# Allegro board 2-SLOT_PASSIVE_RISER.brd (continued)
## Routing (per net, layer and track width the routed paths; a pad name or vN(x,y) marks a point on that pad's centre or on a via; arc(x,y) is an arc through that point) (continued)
I2C_EMC1413_SCL: length 2.7
  TOP w0.117: U2.10 75.92,29.7 76.44,30.23 v1(76.65,30.23) 76.8,30.23 77.05,29.97 R59.2
I2C_EMC1413_SDA: length 2.6
  TOP w0.117: R41.2 77.29,28.8 v1(76.72,28.8) 76.32,29.2 U2.9
I2C_FRU_SCL: length 2.3
  TOP w0.117: U3.6 136.2,44.83 v1(135.27,44.83) 135.01,44.83 R58.2
I2C_FRU_SDA: length 2
  TOP w0.117: U3.5 135.38,46.54 v1(135.32,46.48) R40.2
I2C_MB_RISER_SCL: length 61.6
  TOP w0.117: R27.2 146.55,37.82 v1(146.52,37.8) 146.49,37.82 R57.1
  BOTTOM w0.117: v1(146.52,37.8) 146.65,37.8 147.51,36.93 147.51,27.71 142.28,22.48 121.58,22.48 119.94,20.84 119.94,18.77 118.99,17.82 118.99,14.39 119.94,13.44 119.94,12.06 119.73,11.85 119.73,11.85 119.43,11.56 119.43,11 120.22,10.21 120.22,6.47 119.78,6.03 J3.B5
I2C_MB_RISER_SDA: length 63.9
  TOP w0.117: R17.1 145.76,38.84 146.27,39.34 v1(146.55,39.34) 146.81,39.34 R26.2
  BOTTOM w0.117: v1(146.55,39.34) 145.94,38.73 145.94,37.49 146.72,36.71 146.72,36.71 147.04,36.39 147.04,36.39 147.08,36.35 147.08,28.02 141.91,22.85 121.42,22.85 119.57,21 119.57,18.92 118.61,17.96 118.61,14.25 119.57,13.28 119.57,12.22 119.06,11.71 119.06,10.85 119.85,10.06 119.85,6.63 118.78,5.55 J3.B6
I2C_PCA9548_SCL: length 2.9
  TOP w0.117: R57.2 144.7,37.9 v1(143.12,37.9) U1.22
I2C_PCA9548_SDA: length 3.3
  TOP w0.117: U1.23 143.09,38.55 v1(143.7,39.17) 144.45,39.17 R17.2
I2C_SLOT1_R_SCL: length 5.4
  TOP w0.117: J1.B5 119.78,19.71 121.27,21.21 R9.2
I2C_SLOT1_R_SDA: length 3.4
  TOP w0.117: R10.2 120.26,21.21 118.78,19.73 J1.B6
I2C_SLOT1_SCL: length 20.3
  TOP w0.117: R9.1 121.27,23.62 121.91,24.26 122.67,24.26 122.8,24.38 122.8,25.17 R39.2 123.54,25.91 125.72,25.91 125.97,26.16 125.97,26.92 125.68,27.22 Q4.S 124,27.49 124.32,27.81 125.59,27.81 v1(129.02,31.24) 129.66,31.88 129.66,33.93 R83.2
I2C_SLOT1_SDA: length 20
  TOP w0.117: R10.1 120.26,23.37 120.77,23.88 120.77,25.37 121.06,25.67 R37.2 121.27,25.88 120.57,26.58 Q2.S 120.57,28.05 120.84,28.32 124.96,28.32 v1(126.1,29.46) 126.48,29.46 129.27,32.26 129.27,34.56 R85.2
I2C_SLOT2_R_SCL: length 5.4
  TOP w0.117: J2.B5 119.78,40.28 121.27,41.78 R1.2
I2C_SLOT2_R_SDA: length 3.4
  TOP w0.117: R2.2 120.26,41.78 118.78,40.3 J2.B6
I2C_SLOT2_SCL: length 23.4
  TOP w0.117: R82.2 129.4,36.58 128.18,37.8 128.18,46.81 126.56,48.43 v1(124.07,48.43) Q3.S 122.73,47.45 R38.2 122.14,45.7 121.27,44.83 R1.1
I2C_SLOT2_SDA: length 27.2
  TOP w0.117: R2.1 120.26,45.99 R36.2 119.3,46.95 Q1.S 120.4,49.53 126.35,49.53 v1(126.73,49.15) 128.55,47.33 128.55,38.19 129.15,37.59 R84.2
JTAG_R_TCK: length 8.3
  TOP w0.117: R51.1 120.62,14.1 J1.A5
JTAG_R_TDI: length 9.5
  TOP w0.117: J1.A6 119.56,13.72 125.08,13.72 125.72,13.08 R52.1
JTAG_R_TDO: length 3.7
  TOP w0.117: J1.A7 117.78,12.65 118.48,11.95 R53.1
JTAG_R_TMS: length 1.6
  TOP w0.117: J1.A8 117.46,12.25 R54.1
JTAG_TCK: length 22.3
  TOP w0.117: 127.73,11.05 127.34,11.05 127.22,10.92 125.29,10.92 124.78,11.43 121.55,11.43 121.11,10.99 121.11,10.5 120.09,9.49 120.09,6.47 119.78,6.16 J3.A5 ; 127.73,11.05 R8.2 ; 127.73,11.05 127.73,10.61 127.93,10.41 129.39,10.41 129.76,10.79 129.76,13.99 v1(129.66,14.1) R51.2
JTAG_TDI: length 17.2
  TOP w0.117: J3.A6 118.78,5.68 119.72,6.63 119.72,9.68 120.71,10.67 120.71,11.18 121.34,11.8 v1(126.51,11.8) 127.47,11.8 R5.2 128.53,12.87 R52.2
JTAG_TDO: length 9
  TOP w0.117: J3.A7 117.78,6.17 118.45,6.85 118.45,9.37 119.5,10.41 R6.2 R53.2
JTAG_TMS: length 9
  TOP w0.117: J3.A8 116.78,5.7 118.07,6.99 118.07,10.17 R54.2 R7.2
JTAG_TRST_N: length 20.3
  TOP w0.117: R50.2 v1(113.27,21.59)
  BOTTOM w0.117: v1(113.27,21.59) 113.27,19.68 115.52,17.44 J1.B9 115.78,16.73 114.99,15.94 114.99,14.63 115.78,12.73 J3.B9
PCA9548_ADD0: length 6.4
  TOP w0.117: U1.1 135.54,39.2 134.12,40.62 R55.2 132.68,41.33 v1(131.89,41.33) 131.81,41.33 R12.1
PCA9548_ADD1: length 6.1
  TOP w0.117: U1.2 135.3,38.55 134.46,39.4 v1(134.23,39.4) 133.59,39.4 R13.2 132.85,40.13 131.63,40.13 R14.1
PCA9548_ADD2: length 7.4
  TOP w0.117: U1.21 145.92,37.25 146.5,36.68 v1(146.5,36.17) 146.87,35.79 R56.2 R16.1
PE_CPU1_SLOT1_RX_DN<0>: length 12.2
  TOP w0.127: v1(105.74,7.82) 106.13,7.43 106.13,6.15 105.78,5.8 J3.A17
  IN2 w0.165: J1.A17 106.08,14.32 106.03,14.17 105.87,14.12 105.62,13.87 105.62,13.62 105.62,13.62 105.62,12.65 106.09,8.46 106.09,8.18 v1(105.74,7.82)
PE_CPU1_SLOT1_RX_DN<1>: length 12.1
  TOP w0.127: J3.A22 100.78,5.8 101.13,6.15 101.13,7.43 v1(100.74,7.82)
  IN2 w0.165: J1.A22 101.14,13.66 101.29,13.82 101.51,13.82 101.63,13.7 101.63,12.67 101.09,8.72 101.09,8.18 v1(100.74,7.82)
PE_CPU1_SLOT1_RX_DN<2>: length 12.1
  TOP w0.127: v1(96.74,7.82) 97.13,7.43 97.13,6.15 96.78,5.8 J3.A26
  IN2 w0.165: v1(96.74,7.82) 97.09,8.18 97.09,8.72 97.63,12.67 97.63,13.7 97.51,13.82 97.29,13.82 97.14,13.66 J1.A26
PE_CPU1_SLOT1_RX_DN<3>: length 12.1
  TOP w0.127: v1(92.74,7.82) 93.13,7.43 93.13,6.15 92.78,5.8 J3.A30
  IN2 w0.165: J1.A30 93.14,13.66 93.29,13.82 93.51,13.82 93.63,13.7 93.63,12.67 93.09,8.72 93.09,8.18 v1(92.74,7.82)
PE_CPU1_SLOT1_RX_DN<4>: length 12.1
  TOP w0.127: v1(86.74,7.82) 87.13,7.43 87.13,6.15 86.78,5.8 J3.A36
  IN2 w0.165: J1.A36 87.14,13.66 87.29,13.82 87.51,13.82 87.63,13.7 87.63,12.67 87.09,8.72 87.09,8.18 v1(86.74,7.82)
PE_CPU1_SLOT1_RX_DN<5>: length 12.1
  TOP w0.127: v1(82.74,7.82) 83.13,7.43 83.13,6.15 82.78,5.8 J3.A40
  IN2 w0.165: v1(82.74,7.82) 83.09,8.18 83.09,8.72 83.63,12.67 83.63,13.7 83.51,13.82 83.29,13.82 83.14,13.66 J1.A40
PE_CPU1_SLOT1_RX_DN<6>: length 12.1
  TOP w0.127: v1(78.74,7.82) 79.13,7.43 79.13,6.15 78.78,5.8 J3.A44
  IN2 w0.165: J1.A44 79.14,13.66 79.29,13.82 79.51,13.82 79.63,13.7 79.63,12.67 79.09,8.72 79.09,8.18 v1(78.74,7.82)
PE_CPU1_SLOT1_RX_DN<7>: length 12.1
  TOP w0.127: J3.A48 74.78,5.8 75.13,6.15 75.13,7.43 v1(74.74,7.82)
  IN2 w0.165: v1(74.74,7.82) 75.09,8.18 75.09,8.72 75.63,12.67 75.63,13.7 75.51,13.82 75.29,13.82 75.14,13.66 J1.A48
PE_CPU1_SLOT1_RX_DN<8>: length 12.2
  TOP w0.127: v1(69.74,7.82) 70.13,7.43 70.13,6.15 69.78,5.8 J3.A53
  IN2 w0.165: v1(69.74,7.82) 70.09,8.18 70.09,8.46 69.62,12.65 69.62,13.62 69.62,13.62 69.62,13.87 69.87,14.12 70.03,14.17 70.08,14.32 J1.A53
PE_CPU1_SLOT1_RX_DN<9>: length 12.2
  TOP w0.127: J3.A57 65.78,5.8 66.13,6.15 66.13,7.43 v1(65.74,7.82)
  IN2 w0.165: J1.A57 66.08,14.32 66.03,14.17 65.87,14.12 65.62,13.87 65.62,13.62 65.62,13.62 65.62,12.65 66.09,8.46 66.09,8.18 v1(65.74,7.82)
PE_CPU1_SLOT1_RX_DN<10>: length 12.2
  TOP w0.127: J3.A61 61.78,5.8 62.13,6.15 62.13,7.43 v1(61.74,7.82)
  IN2 w0.165: J1.A61 62.08,14.32 62.03,14.17 61.87,14.12 61.62,13.87 61.62,13.62 61.62,13.62 61.62,12.65 62.09,8.46 62.09,8.18 v1(61.74,7.82)
PE_CPU1_SLOT1_RX_DN<11>: length 12.2
  TOP w0.127: J3.A65 57.78,5.8 58.13,6.15 58.13,7.43 v1(57.74,7.82)
  IN2 w0.165: J1.A65 58.08,14.32 58.03,14.17 57.87,14.12 57.62,13.87 57.62,13.62 57.62,13.62 57.62,12.65 58.09,8.46 58.09,8.18 v1(57.74,7.82)
PE_CPU1_SLOT1_RX_DN<12>: length 12.1
  TOP w0.127: v1(53.74,7.82) 54.04,7.52 54.04,6.07 53.78,5.81 J3.A69
  IN2 w0.165: J1.A69 54.08,14.32 54.03,14.17 53.87,14.12 53.62,13.87 53.62,13.62 53.62,13.62 53.62,12.65 54.09,8.46 54.09,8.18 v1(53.74,7.82)
PE_CPU1_SLOT1_RX_DN<13>: length 12.1
  TOP w0.127: J3.A73 49.78,5.8 50.07,6.09 50.06,6.1 50.06,7.5 v1(49.74,7.82)
  IN2 w0.165: J1.A73 50.08,14.32 50.03,14.17 49.87,14.12 49.62,13.87 49.62,13.62 49.62,13.62 49.62,12.65 50.09,8.46 50.09,8.18 v1(49.74,7.82)
PE_CPU1_SLOT1_RX_DN<14>: length 12.2
  TOP w0.127: v1(45.74,7.82) 46.13,7.43 46.13,6.2 45.78,5.84 J3.A77
  IN2 w0.165: v1(45.74,7.82) 46.09,8.18 46.09,8.46 45.62,12.65 45.62,13.62 45.62,13.62 45.62,13.87 45.87,14.12 46.03,14.17 46.08,14.32 J1.A77
PE_CPU1_SLOT1_RX_DN<15>: length 12.2
  TOP w0.127: J3.A81 41.78,5.8 42.13,6.15 42.13,7.43 v1(41.74,7.82)
  IN2 w0.165: v1(41.74,7.82) 42.09,8.18 42.09,8.46 41.62,12.65 41.62,13.62 41.62,13.62 41.62,13.87 41.87,14.12 42.03,14.17 42.08,14.32 J1.A81
PE_CPU1_SLOT1_RX_DP<0>: length 12.1
  TOP w0.127: v1(106.75,7.82) 106.42,7.49 106.42,6.15 106.78,5.8 J3.A16
  IN2 w0.165: J1.A16 106.33,13.84 106.15,13.89 106.03,13.85 105.92,13.75 105.92,12.67 106.16,10.57 106.4,8.48 106.4,8.18 v1(106.75,7.82)
PE_CPU1_SLOT1_RX_DP<1>: length 12.2
  TOP w0.127: J3.A21 101.78,5.8 101.42,6.15 101.42,7.49 v1(101.75,7.82)
  IN2 w0.165: J1.A21 101.46,14.31 101.51,14.16 101.73,14.05 101.93,13.85 101.93,12.65 101.4,8.7 101.4,8.18 v1(101.75,7.82)
PE_CPU1_SLOT1_RX_DP<2>: length 12.2
  TOP w0.127: v1(97.75,7.82) 97.42,7.49 97.42,6.15 97.78,5.8 J3.A25
  IN2 w0.165: v1(97.75,7.82) 97.4,8.18 97.4,8.7 97.93,12.65 97.93,13.85 97.73,14.05 97.51,14.16 97.46,14.31 J1.A25
PE_CPU1_SLOT1_RX_DP<3>: length 12.2
  TOP w0.127: v1(93.75,7.82) 93.42,7.49 93.42,6.15 93.78,5.8 J3.A29
  IN2 w0.165: J1.A29 93.46,14.31 93.51,14.16 93.73,14.05 93.93,13.85 93.93,12.65 93.4,8.7 93.4,8.18 v1(93.75,7.82)
PE_CPU1_SLOT1_RX_DP<4>: length 12.2
  TOP w0.127: J3.A35 87.78,5.8 87.42,6.15 87.42,7.49 v1(87.75,7.82)
  IN2 w0.165: v1(87.75,7.82) 87.4,8.18 87.4,8.7 87.93,12.65 87.93,13.85 87.73,14.05 87.51,14.16 87.46,14.31 J1.A35
PE_CPU1_SLOT1_RX_DP<5>: length 12.2
  TOP w0.127: v1(83.75,7.82) 83.42,7.49 83.42,6.15 83.78,5.8 J3.A39
  IN2 w0.165: J1.A39 83.46,14.31 83.51,14.16 83.73,14.05 83.93,13.85 83.93,12.65 83.4,8.7 83.4,8.18 v1(83.75,7.82)
PE_CPU1_SLOT1_RX_DP<6>: length 12.2
  TOP w0.127: J3.A43 79.78,5.8 79.42,6.15 79.42,7.49 v1(79.75,7.82)
  IN2 w0.165: J1.A43 79.46,14.31 79.51,14.16 79.73,14.05 79.93,13.85 79.93,12.65 79.4,8.7 79.4,8.18 v1(79.75,7.82)
PE_CPU1_SLOT1_RX_DP<7>: length 12.2
  TOP w0.127: J3.A47 75.78,5.8 75.42,6.15 75.42,7.49 v1(75.75,7.82)
  IN2 w0.165: v1(75.75,7.82) 75.4,8.18 75.4,8.7 75.93,12.65 75.93,13.85 75.73,14.05 75.51,14.16 75.46,14.31 J1.A47
PE_CPU1_SLOT1_RX_DP<8>: length 12.1
  TOP w0.127: J3.A52 70.78,5.8 70.42,6.15 70.42,7.49 v1(70.75,7.82)
  IN2 w0.165: v1(70.75,7.82) 70.4,8.18 70.4,8.48 70.16,10.57 69.92,12.67 69.92,13.75 70.03,13.85 70.15,13.89 70.33,13.84 J1.A52
PE_CPU1_SLOT1_RX_DP<9>: length 12.1
  TOP w0.127: J3.A56 66.78,5.8 66.42,6.15 66.42,7.49 v1(66.75,7.82)
  IN2 w0.165: v1(66.75,7.82) 66.4,8.18 66.4,8.48 66.16,10.57 65.92,12.67 65.92,13.75 66.03,13.85 66.15,13.89 66.33,13.84 J1.A56
PE_CPU1_SLOT1_RX_DP<10>: length 12.1
  TOP w0.127: v1(62.75,7.82) 62.42,7.49 62.42,6.15 62.78,5.8 J3.A60
  IN2 w0.165: v1(62.75,7.82) 62.4,8.18 62.4,8.48 62.16,10.57 61.92,12.67 61.92,13.75 62.03,13.85 62.15,13.89 62.33,13.84 J1.A60
PE_CPU1_SLOT1_RX_DP<11>: length 12.1
  TOP w0.127: J3.A64 58.78,5.8 58.42,6.15 58.42,7.49 v1(58.75,7.82)
  IN2 w0.165: v1(58.75,7.82) 58.4,8.18 58.4,8.48 58.16,10.57 57.92,12.67 57.92,13.75 58.03,13.85 58.15,13.89 58.33,13.84 J1.A64
PE_CPU1_SLOT1_RX_DP<12>: length 12.2
  TOP w0.127: J3.A68 54.78,5.66 54.33,6.11 54.33,7.4 v1(54.75,7.82)
  IN2 w0.165: v1(54.75,7.82) 54.4,8.18 54.4,8.48 54.16,10.57 53.92,12.67 53.92,13.75 54.03,13.85 54.15,13.89 54.33,13.84 J1.A68
PE_CPU1_SLOT1_RX_DP<13>: length 12.2
  TOP w0.127: v1(50.75,7.82) 50.36,7.43 50.36,6.12 50.78,5.7 J3.A72
  IN2 w0.165: J1.A72 50.33,13.84 50.15,13.89 50.03,13.85 49.92,13.75 49.92,12.67 50.16,10.57 50.4,8.48 50.4,8.18 v1(50.75,7.82)
PE_CPU1_SLOT1_RX_DP<14>: length 12.1
  TOP w0.127: v1(46.75,7.82) 46.42,7.49 46.42,6.21 46.78,5.85 J3.A76
  IN2 w0.165: v1(46.75,7.82) 46.4,8.18 46.4,8.48 46.16,10.57 45.92,12.67 45.92,13.75 46.03,13.85 46.15,13.89 46.33,13.84 J1.A76
PE_CPU1_SLOT1_RX_DP<15>: length 12.1
  TOP w0.127: J3.A80 42.78,5.8 42.42,6.15 42.42,7.49 v1(42.75,7.82)
  IN2 w0.165: v1(42.75,7.82) 42.4,8.18 42.4,8.48 42.16,10.57 41.92,12.67 41.92,13.75 42.03,13.85 42.15,13.89 42.33,13.84 J1.A80
PE_CPU1_SLOT1_TX_DN<0>: length 16.5
  BOTTOM w0.127: J1.B15 108.19,18.27 108.32,18.31 108.5,18.31 108.63,18.18 108.63,14.77 108.57,14.63 108.45,14.43 108.02,13.91 107.8,13.56 107.68,13.31 107.64,13.08 107.64,12.31 108.13,6.18 107.78,5.82 J3.B15
PE_CPU1_SLOT1_TX_DN<1>: length 16.6
  BOTTOM w0.127: J1.B20 103.06,18.87 103.06,18.75 102.63,18.31 102.63,14.71 102.68,14.59 102.68,14.59 102.72,14.49 102.86,14.26 103.29,13.74 103.49,13.42 103.59,13.22 103.62,13.05 103.62,12.32 103.13,6.18 102.77,5.82 J3.B20
PE_CPU1_SLOT1_TX_DN<2>: length 16.6
  BOTTOM w0.127: J1.B24 99.07,18.84 99.07,18.75 98.63,18.3 98.63,14.71 98.68,14.59 98.68,14.59 98.72,14.49 98.86,14.26 99.29,13.74 99.49,13.42 99.59,13.22 99.62,13.05 99.62,12.32 99.13,6.18 98.77,5.82 J3.B24
PE_CPU1_SLOT1_TX_DN<3>: length 16.6
  BOTTOM w0.127: J1.B28 95.06,18.87 95.06,18.77 94.63,18.34 94.63,14.71 94.68,14.59 94.68,14.59 94.72,14.49 94.86,14.26 95.29,13.74 95.49,13.42 95.59,13.22 95.62,13.05 95.62,12.32 95.13,6.18 95.13,6.18 94.77,5.82 J3.B28
PE_CPU1_SLOT1_TX_DN<4>: length 16.6
  BOTTOM w0.127: J3.B34 88.77,5.82 89.13,6.18 89.13,6.18 89.62,12.32 89.62,13.05 89.59,13.22 89.49,13.42 89.29,13.74 88.86,14.26 88.79,14.37 88.72,14.49 88.63,14.71 88.63,18.33 89.07,18.77 89.07,18.86 J1.B34
PE_CPU1_SLOT1_TX_DN<5>: length 16.6
  BOTTOM w0.127: J3.B38 84.77,5.82 85.13,6.18 85.13,6.18 85.62,12.32 85.62,13.05 85.59,13.22 85.49,13.42 85.29,13.74 84.86,14.26 84.72,14.49 84.68,14.59 84.68,14.59 84.63,14.71 84.63,18.3 85.08,18.75 85.08,18.84 J1.B38
PE_CPU1_SLOT1_TX_DN<6>: length 16.6
  BOTTOM w0.127: J3.B42 80.77,5.82 81.13,6.18 81.13,6.18 81.62,12.32 81.62,13.05 81.59,13.22 81.49,13.42 81.29,13.74 80.86,14.26 80.72,14.49 80.63,14.71 80.63,18.33 81.07,18.77 81.07,18.86 J1.B42
PE_CPU1_SLOT1_TX_DN<7>: length 16.6
  BOTTOM w0.127: J3.B46 76.77,5.82 77.13,6.18 77.13,6.18 77.62,12.32 77.62,13.05 77.59,13.22 77.49,13.42 77.29,13.74 76.86,14.26 76.72,14.49 76.63,14.71 76.63,18.32 77.05,18.75 77.05,18.89 J1.B46
PE_CPU1_SLOT1_TX_DN<8>: length 16.5
  BOTTOM w0.127: J1.B51 72.18,18.26 72.35,18.31 72.5,18.31 72.63,18.18 72.63,14.77 72.57,14.63 72.45,14.43 72.02,13.91 71.8,13.56 71.68,13.31 71.64,13.08 71.64,12.31 72.13,6.18 71.78,5.82 J3.B51
PE_CPU1_SLOT1_TX_DN<9>: length 16.5
  BOTTOM w0.127: J1.B55 68.18,18.24 68.39,18.31 68.54,18.31 68.63,18.22 68.63,14.77 68.57,14.63 68.45,14.43 68.02,13.91 67.8,13.56 67.68,13.31 67.64,13.08 67.64,12.31 68.13,6.18 67.78,5.82 J3.B55
PE_CPU1_SLOT1_TX_DN<10>: length 16.5
  BOTTOM w0.127: J1.B59 64.18,18.25 64.3,18.29 64.52,18.29 64.63,18.18 64.63,14.77 64.57,14.63 64.45,14.43 64.02,13.91 63.8,13.56 63.68,13.31 63.64,13.08 63.64,12.31 64.13,6.18 63.78,5.82 J3.B59
PE_CPU1_SLOT1_TX_DN<11>: length 16.5
  BOTTOM w0.127: J3.B63 59.78,5.82 60.13,6.18 59.64,12.31 59.64,13.08 59.68,13.31 59.8,13.56 60.02,13.91 60.45,14.43 60.57,14.63 60.63,14.77 60.63,18.14 60.48,18.29 60.29,18.29 60.18,18.25 J1.B63
PE_CPU1_SLOT1_TX_DN<12>: length 16.5
  BOTTOM w0.127: J1.B67 56.18,18.26 56.35,18.31 56.47,18.31 56.63,18.16 56.63,14.77 56.57,14.63 56.45,14.43 56.02,13.91 55.8,13.56 55.68,13.31 55.64,13.08 55.64,12.31 56.13,6.18 55.78,5.82 J3.B67
PE_CPU1_SLOT1_TX_DN<13>: length 16.5
  BOTTOM w0.127: J1.B71 52.17,18.23 52.34,18.29 52.51,18.29 52.62,18.18 52.62,14.74 52.57,14.63 52.45,14.43 52.02,13.91 51.8,13.56 51.68,13.31 51.64,13.08 51.64,12.31 52.13,6.18 51.78,5.82 J3.B71
PE_CPU1_SLOT1_TX_DN<14>: length 16.5
  BOTTOM w0.127: J1.B75 48.21,18.31 48.3,18.34 48.44,18.34 48.63,18.15 48.63,14.77 48.57,14.63 48.45,14.43 48.02,13.91 47.8,13.56 47.68,13.31 47.64,13.08 47.64,12.31 48.13,6.18 47.78,5.82 J3.B75
PE_CPU1_SLOT1_TX_DN<15>: length 16.5
  BOTTOM w0.127: J1.B79 44.21,18.3 44.31,18.34 44.43,18.34 44.63,18.14 44.63,14.77 44.57,14.63 44.45,14.43 44.02,13.91 43.8,13.56 43.68,13.31 43.64,13.08 43.64,12.31 44.13,6.18 43.78,5.82 J3.B79
PE_CPU1_SLOT1_TX_DP<0>: length 16.6
  BOTTOM w0.127: J3.B14 108.78,5.82 108.42,6.18 108.42,6.18 107.93,12.32 107.93,13.05 107.96,13.22 108.06,13.42 108.26,13.74 108.69,14.26 108.83,14.49 108.92,14.71 108.92,18.3 108.47,18.75 108.47,18.83 J1.B14
PE_CPU1_SLOT1_TX_DP<1>: length 16.5
  BOTTOM w0.127: J1.B19 103.37,18.24 103.24,18.29 103.02,18.29 102.92,18.19 102.92,14.77 102.98,14.63 103.1,14.43 103.53,13.91 103.75,13.56 103.87,13.31 103.91,13.08 103.91,12.31 103.42,6.18 103.77,5.82 J3.B19
PE_CPU1_SLOT1_TX_DP<2>: length 16.5
  BOTTOM w0.127: J1.B23 99.37,18.26 99.2,18.31 99.06,18.31 98.92,18.18 98.92,14.77 98.98,14.63 99.1,14.43 99.53,13.91 99.75,13.56 99.87,13.31 99.91,13.08 99.91,12.31 99.42,6.18 99.77,5.82 J3.B23
PE_CPU1_SLOT1_TX_DP<3>: length 16.5
  BOTTOM w0.127: J3.B27 95.77,5.82 95.42,6.18 95.91,12.31 95.91,13.08 95.87,13.31 95.75,13.56 95.53,13.91 95.1,14.43 94.98,14.63 94.92,14.77 94.92,18.22 95.02,18.31 95.19,18.31 95.37,18.25 J1.B27
PE_CPU1_SLOT1_TX_DP<4>: length 16.5
  BOTTOM w0.127: J3.B33 89.77,5.82 89.42,6.18 89.91,12.31 89.91,13.08 89.87,13.31 89.75,13.56 89.53,13.91 89.1,14.43 89.05,14.52 88.98,14.63 88.92,14.77 88.92,18.21 89.02,18.31 89.19,18.31 89.37,18.26 J1.B33
PE_CPU1_SLOT1_TX_DP<5>: length 16.5
  BOTTOM w0.127: J1.B37 85.36,18.27 85.23,18.31 85.06,18.31 84.92,18.18 84.92,14.77 84.98,14.63 85.1,14.43 85.53,13.91 85.75,13.56 85.87,13.31 85.91,13.08 85.91,12.31 85.42,6.18 85.77,5.82 J3.B37
PE_CPU1_SLOT1_TX_DP<6>: length 16.5
  BOTTOM w0.127: J1.B41 81.37,18.25 81.17,18.31 81.02,18.31 80.92,18.21 80.92,14.77 80.98,14.63 81.1,14.43 81.53,13.91 81.75,13.56 81.87,13.31 81.91,13.08 81.91,12.31 81.42,6.18 81.77,5.82 J3.B41
PE_CPU1_SLOT1_TX_DP<7>: length 16.5
  BOTTOM w0.127: J1.B45 77.37,18.25 77.18,18.31 77.03,18.31 76.92,18.2 76.92,14.77 76.98,14.63 77.1,14.43 77.53,13.91 77.75,13.56 77.87,13.31 77.91,13.08 77.91,12.31 77.42,6.18 77.77,5.82 J3.B45
PE_CPU1_SLOT1_TX_DP<8>: length 16.6
  BOTTOM w0.127: J3.B50 72.78,5.82 72.42,6.18 72.42,6.18 71.93,12.32 71.93,13.05 71.96,13.22 72.06,13.42 72.26,13.74 72.69,14.26 72.83,14.49 72.92,14.71 72.92,18.3 72.48,18.75 72.48,18.85 J1.B50
PE_CPU1_SLOT1_TX_DP<9>: length 16.6
  BOTTOM w0.127: J3.B54 68.78,5.82 68.42,6.18 68.42,6.18 67.93,12.32 67.93,13.05 67.96,13.22 68.06,13.42 68.26,13.74 68.69,14.26 68.83,14.49 68.92,14.71 68.92,18.34 68.49,18.77 68.49,18.87 J1.B54
PE_CPU1_SLOT1_TX_DP<10>: length 16.6
  BOTTOM w0.127: J1.B58 64.48,18.85 64.48,18.75 64.92,18.3 64.92,14.71 64.83,14.49 64.69,14.26 64.26,13.74 64.06,13.42 63.96,13.22 63.93,13.05 63.93,12.32 64.42,6.18 64.42,6.18 64.78,5.82 J3.B58
PE_CPU1_SLOT1_TX_DP<11>: length 16.6
  BOTTOM w0.127: J1.B62 60.49,18.87 60.49,18.69 60.92,18.26 60.92,14.71 60.83,14.49 60.69,14.26 60.26,13.74 60.06,13.42 59.96,13.22 59.93,13.05 59.93,12.32 60.42,6.18 60.42,6.18 60.78,5.82 J3.B62
PE_CPU1_SLOT1_TX_DP<12>: length 16.6
  BOTTOM w0.127: J3.B66 56.78,5.82 56.42,6.18 56.42,6.18 55.93,12.32 55.93,13.05 55.96,13.22 56.06,13.42 56.26,13.74 56.69,14.26 56.83,14.49 56.92,14.71 56.92,18.28 56.48,18.72 56.48,18.85 J1.B66
PE_CPU1_SLOT1_TX_DP<13>: length 16.6
  BOTTOM w0.127: J3.B70 52.78,5.82 52.42,6.18 51.93,12.32 51.93,13.05 51.96,13.22 52.06,13.42 52.26,13.74 52.69,14.26 52.83,14.49 52.91,14.68 52.91,18.3 52.5,18.71 52.48,18.85 J1.B70
PE_CPU1_SLOT1_TX_DP<14>: length 16.6
  BOTTOM w0.127: J3.B74 48.78,5.82 48.42,6.18 48.42,6.18 47.93,12.32 47.93,13.05 47.96,13.22 48.06,13.42 48.26,13.74 48.62,14.17 48.64,14.18 48.69,14.26 48.79,14.42 48.83,14.49 48.92,14.71 48.92,18.28 48.48,18.72 48.48,18.85 J1.B74
PE_CPU1_SLOT1_TX_DP<15>: length 16.6
  BOTTOM w0.127: J1.B78 44.49,18.87 44.49,18.69 44.92,18.26 44.92,14.71 44.83,14.5 44.69,14.26 44.26,13.74 44.06,13.42 43.96,13.22 43.93,13.05 43.93,12.32 44.42,6.18 44.42,6.18 44.78,5.82 J3.B78
PE_CPU1_SLOT2_RX_DN<0>: length 35.9
  TOP w0.127: J4.3 100.47,64.31 100.63,64.47 100.63,65.15 v1(100.37,65.41)
  IN2 w0.165: J2.A17 106.13,34.54 106.36,34.47 106.5,34.54 106.65,34.69 106.65,38.1 105.65,39.09 105.65,40.04 105.66,42.71 100.6,57.92 100.6,60.85 100.41,61.05 100.41,61.71 100.6,61.91 100.6,62.57 100.41,62.76 100.41,63.42 100.6,63.62 100.6,65.17 v1(100.37,65.41)
PE_CPU1_SLOT2_RX_DN<1>: length 38.3
  TOP w0.127: v1(98.62,66.88) 98.83,66.68 98.83,64.47 98.67,64.31 J4.6
  IN2 w0.165: v1(98.62,66.88) 98.83,66.68 98.83,58.61 101.62,43.76 101.62,39.3 100.6,38.29 100.6,34.57 100.87,34.3 101.06,34.2 101.13,33.98 J2.A22
PE_CPU1_SLOT2_RX_DN<2>: length 37.4
  TOP w0.127: v1(96.77,65.41) 97.03,65.15 97.03,64.47 96.87,64.31 J4.9
  IN2 w0.165: v1(96.77,65.41) 97,65.18 97,64.27 97,64.26 97,58.99 96.28,54.9 96.72,50.62 97.21,45.83 97.62,45.5 98.44,45.58 98.66,45.41 98.68,45.14 98.51,44.92 97.69,44.84 97.36,44.43 97.63,41.81 97.63,40.93 97.63,39.32 96.6,38.29 96.6,34.57 96.87,34.3 97.06,34.2 97.13,33.98 J2.A26
PE_CPU1_SLOT2_RX_DN<3>: length 38.1
  TOP w0.127: J4.12 95.07,64.31 95.23,64.47 95.23,66.68 v1(95.02,66.88)
  IN2 w0.165: J2.A30 93.13,33.98 93.06,34.2 92.87,34.3 92.6,34.57 92.6,38.29 93.62,39.31 94.48,54.92 95.25,59.29 95.25,66.65 v1(95.02,66.88)
PE_CPU1_SLOT2_RX_DN<4>: length 39.2
  TOP w0.127: J4.15 93.27,64.31 93.43,64.47 93.43,65.15 v1(93.17,65.41)
  IN2 w0.165: v1(93.17,65.41) 93.4,65.18 93.4,64.2 93.24,63.32 91.85,59.95 91.83,59.89 91.63,59.21 91.31,58.43 90.03,54.57 88.63,46.6 88.91,46.19 90.33,45.94 90.5,45.7 90.46,45.43 90.23,45.27 88.81,45.52 88.38,45.22 87.62,40.9 87.62,39.31 86.63,38.32 86.63,34.53 86.87,34.3 87.06,34.2 87.13,33.98 J2.A36
PE_CPU1_SLOT2_RX_DN<5>: length 39.5
  TOP w0.127: v1(91.41,66.88) 91.63,66.67 91.63,64.47 91.47,64.31 J4.18
  IN2 w0.165: v1(91.41,66.88) 91.63,66.66 91.63,64.64 91.19,62.15 90.57,61.02 90.06,59.93 89.61,58.79 86.27,50.32 83.98,43.65 83.63,41.65 83.63,39.32 82.62,38.31 82.62,34.55 82.87,34.3 83.06,34.2 83.13,33.98 J2.A40
PE_CPU1_SLOT2_RX_DN<6>: length 40.6
  TOP w0.127: J4.21 89.67,64.31 89.83,64.47 89.83,65.15 v1(89.57,65.41)
  IN2 w0.165: v1(89.57,65.41) 89.8,65.18 89.8,64.49 89.56,63.12 86.36,59.92 81.96,48.62 81.96,48.61 81.06,46.31 81.26,45.86 82.38,45.42 82.5,45.15 82.4,44.89 82.15,44.78 81.03,45.22 80.55,45 80.11,43.87 79.79,43.17 79.62,42.3 79.61,40.65 79.62,40.62 79.62,39.31 78.63,38.32 78.63,34.53 78.87,34.3 79.06,34.2 79.13,33.98 J2.A44
PE_CPU1_SLOT2_RX_DN<7>: length 41.3
  TOP w0.127: J4.24 87.87,64.31 88.03,64.47 88.03,66.66 v1(87.8,66.88)
  IN2 w0.165: J2.A48 75.13,33.98 75.06,34.2 74.87,34.3 74.6,34.57 74.6,38.29 75.63,39.32 75.63,42.69 81.5,53.29 88.03,64.57 88.03,66.65 88.03,66.65 v1(87.8,66.88)
PE_CPU1_SLOT2_RX_DN<8>: length 36
  TOP w0.127: v1(66.02,65.41) 66.28,65.15 66.28,64.47 66.12,64.31 J5.3
  IN2 w0.165: v1(66.02,65.41) 66.25,65.17 66.25,64.68 66.42,63.73 66.42,63.72 66.49,63.36 67.45,61.03 68.18,60.73 69.22,58.2 69.29,57.37 68.58,53.33 68.65,52.77 69.07,47.51 68.91,47.33 68.97,46.6 69.15,46.44 69.2,45.79 69.06,45.63 69.13,44.85 69.29,44.72 69.6,40.73 69.61,40.52 69.61,40.51 69.61,39.29 70.6,38.3 70.6,34.64 70.5,34.54 70.36,34.47 70.13,34.54 J2.A53
PE_CPU1_SLOT2_RX_DN<9>: length 38.4
  TOP w0.127: J5.6 64.32,64.31 64.48,64.47 64.48,66.68 v1(64.27,66.88)
  IN2 w0.165: J2.A57 66.13,34.54 66.36,34.47 66.5,34.54 66.65,34.69 66.65,38.26 65.61,39.29 65.61,42.8 65.72,44.07 65.57,44.25 65.63,44.91 65.81,45.06 65.87,45.72 65.71,45.9 65.77,46.56 65.95,46.71 66.73,55.66 66.41,58.16 66.41,58.17 66.41,58.21 66.36,58.45 65.91,60.99 65.87,61.08 65.11,62.47 64.52,64.5 64.48,65.05 64.48,66.68 v1(64.27,66.88)
PE_CPU1_SLOT2_RX_DN<10>: length 36.1
  TOP w0.127: v1(62.42,65.41) 62.68,65.15 62.68,64.47 62.52,64.31 J5.9
  IN2 w0.165: v1(62.42,65.41) 62.65,65.18 62.65,64.68 62.82,63.68 63.05,63.12 63.26,62.45 64.08,60.75 64.22,60.42 65.14,55.21 63.19,47.87 62.97,47.75 62.8,47.11 62.93,46.89 62.76,46.25 62.54,46.12 62.37,45.49 62.5,45.27 62.33,44.63 62.11,44.5 61.94,43.86 62.07,43.65 61.54,41.64 61.54,40.51 61.61,40.44 61.61,39.25 62.6,38.26 62.6,34.64 62.5,34.54 62.36,34.47 62.13,34.54 J2.A61
PE_CPU1_SLOT2_RX_DN<11>: length 38.4
  TOP w0.127: J5.12 60.72,64.32 60.88,64.47 60.88,66.68 v1(60.67,66.88)
  IN2 w0.165: v1(60.67,66.88) 60.89,66.66 60.89,66.2 60.69,65.08 61.32,61.51 58.54,48.94 58.32,48.8 58.18,48.16 58.32,47.94 58.18,47.29 57.96,47.15 57.82,46.5 57.96,46.28 57.76,45.4 57.62,41.58 57.62,39.24 58.59,38.27 58.59,34.63 58.5,34.54 58.36,34.47 58.13,34.54 J2.A65
PE_CPU1_SLOT2_RX_DN<12>: length 37.6
  TOP w0.127: v1(58.82,65.41) 59.08,65.15 59.08,64.47 58.92,64.31 J5.15
  IN2 w0.165: J2.A69 54.13,34.54 54.36,34.47 54.5,34.54 54.62,34.66 54.62,38.23 53.64,39.22 53.64,40.44 53.33,40.74 53.33,42.92 53.84,43.65 53.79,43.92 53.51,44.12 53.42,44.64 53.72,45.07 54.24,45.16 54.52,44.96 54.79,45.01 55.05,45.39 55.34,46.23 55.23,46.45 55.44,47.08 55.66,47.18 55.87,47.81 55.76,48.03 55.97,48.65 56.19,48.76 58.95,56.97 59.17,58.15 59.01,59.31 59.5,62.08 59.05,64.7 59.05,65.18 v1(58.82,65.41)
PE_CPU1_SLOT2_RX_DN<13>: length 39.8
  TOP w0.127: v1(57.06,66.88) 57.28,66.67 57.28,64.47 57.12,64.31 J5.18
  IN2 w0.165: v1(57.06,66.88) 57.29,66.56 57.29,58.82 57.22,58.36 51.18,46.58 51.18,46.58 50.92,46.5 50.7,46.08 50.71,46.08 50.79,45.82 50.58,45.41 50.57,45.4 50.31,45.32 50.1,44.91 50.1,44.9 50.19,44.64 49.62,43.53 49.62,39.24 50.62,38.24 50.62,34.66 50.5,34.54 50.36,34.47 50.13,34.54 J2.A73
PE_CPU1_SLOT2_RX_DN<14>: length 38.8
  TOP w0.127: v1(55.22,65.41) 55.48,65.15 55.48,64.47 55.32,64.31 J5.21
  IN2 w0.165: J2.A77 46.13,34.54 46.36,34.47 46.46,34.52 46.62,34.68 46.62,38.24 45.63,39.22 45.63,40.59 45.62,43.13 45.95,43.65 45.88,43.91 45.88,43.92 46.13,44.31 46.39,44.37 46.4,44.38 46.65,44.77 46.58,45.03 46.58,45.04 46.83,45.43 47.09,45.5 47.1,45.5 48.15,47.18 50.89,51.57 50.51,53.23 53.19,57.52 54.85,57.91 55.16,58.39 55.26,58.56 55.45,59.63 55.45,65.18 v1(55.22,65.41)
PE_CPU1_SLOT2_RX_DN<15>: length 41.3
  TOP w0.127: J5.24 53.52,64.31 53.68,64.47 53.68,66.66 v1(53.45,66.88)
  IN2 w0.165: v1(53.45,66.88) 53.68,66.65 53.68,65.08 53.68,65.05 53.68,64.03 53.3,62.41 43.97,47.15 43.72,47.09 43.37,46.53 43.44,46.28 43.09,45.71 42.84,45.65 42.49,45.09 42.55,44.84 41.62,43.31 41.62,39.22 42.62,38.22 42.62,34.66 42.5,34.54 42.36,34.47 42.13,34.54 J2.A81
PE_CPU1_SLOT2_RX_DP<0>: length 35.9
  TOP w0.127: v1(101.13,65.41) 100.92,65.2 100.92,64.47 101.07,64.31 J4.2
  IN2 w0.165: v1(101.13,65.41) 101.12,65.41 100.91,65.19 100.91,57.97 105.96,42.76 105.96,42.07 105.96,41.38 105.96,40.04 105.96,39.21 106.95,38.22 106.95,34.56 106.68,34.3 106.49,34.2 106.42,33.98 J2.A16
PE_CPU1_SLOT2_RX_DP<1>: length 38.3
  TOP w0.127: v1(99.39,66.88) 99.12,66.62 99.12,64.47 99.27,64.31 J4.5
  IN2 w0.165: v1(99.39,66.88) 99.13,66.63 99.13,64.17 99.3,64 99.3,63.28 99.13,63.11 99.13,62.45 99.28,62.3 99.28,61.54 99.13,61.39 99.13,58.64 101.92,43.79 101.92,39.18 100.9,38.16 100.9,34.69 101.05,34.54 101.19,34.47 101.42,34.54 J2.A21
PE_CPU1_SLOT2_RX_DP<2>: length 37.3
  TOP w0.127: J4.8 97.47,64.31 97.32,64.47 97.32,65.2 v1(97.53,65.41)
  IN2 w0.165: v1(97.53,65.41) 97.3,65.18 97.3,64.29 97.3,64.29 97.3,63.67 97.47,63.5 97.47,62.84 97.3,62.68 97.3,62.02 97.47,61.85 97.47,61.19 97.3,61.02 97.3,58.96 96.58,54.89 97.02,50.65 97.5,45.98 97.71,45.81 98.54,45.9 98.94,45.56 99,45.04 98.67,44.64 97.84,44.55 97.67,44.34 97.93,41.83 97.93,41.81 97.93,40.93 97.93,39.19 96.9,38.16 96.9,34.69 97.05,34.54 97.19,34.47 97.42,34.54 J2.A25
PE_CPU1_SLOT2_RX_DP<3>: length 38.1
  TOP w0.127: J4.11 95.67,64.31 95.52,64.47 95.52,66.62 v1(95.78,66.88)
  IN2 w0.165: v1(95.78,66.88) 95.55,66.65 95.55,63.82 95.63,63.74 95.72,63.65 95.72,62.99 95.63,62.9 95.55,62.82 95.55,62.16 95.63,62.07 95.72,61.99 95.72,61.33 95.63,61.24 95.55,61.16 95.55,59.26 94.78,54.88 93.92,39.18 92.9,38.16 92.9,34.69 93.05,34.54 93.19,34.47 93.42,34.54 J2.A29
PE_CPU1_SLOT2_RX_DP<4>: length 39.2
  TOP w0.127: J4.14 93.87,64.31 93.72,64.47 93.72,65.2 v1(93.93,65.41)
  IN2 w0.165: J2.A35 87.42,34.54 87.19,34.47 87.05,34.54 86.93,34.66 86.93,38.19 87.92,39.18 87.92,40.87 88.66,45.04 88.88,45.2 90.3,44.95 90.73,45.25 90.82,45.77 90.51,46.22 89.09,46.47 88.95,46.67 90.33,54.5 91.59,58.32 91.92,59.11 92.12,59.81 92.14,59.85 92.3,60.24 92.56,60.35 92.81,60.96 92.7,61.22 92.95,61.83 93.21,61.94 93.47,62.55 93.36,62.81 93.53,63.24 93.7,64.18 93.7,65.18 v1(93.93,65.41)
PE_CPU1_SLOT2_RX_DP<5>: length 39.5
  TOP w0.127: J4.17 92.07,64.31 91.92,64.47 91.92,66.63 v1(92.17,66.88)
  IN2 w0.165: J2.A39 83.42,34.54 83.19,34.47 83.05,34.54 82.92,34.67 82.92,38.18 83.94,39.2 83.94,41.62 84.27,43.58 84.77,45.03 85.03,45.15 85.28,45.9 85.16,46.15 85.37,46.78 85.64,46.91 85.89,47.64 85.76,47.91 86.55,50.21 89.89,58.68 89.89,58.68 90.34,59.81 90.84,60.88 91.48,62.05 91.94,64.62 91.94,66.65 v1(92.17,66.88)
PE_CPU1_SLOT2_RX_DP<6>: length 40.5
  TOP w0.127: v1(90.33,65.41) 90.12,65.2 90.12,64.47 90.27,64.31 J4.20
  IN2 w0.165: J2.A43 79.42,34.54 79.19,34.47 79.05,34.54 78.93,34.66 78.93,38.19 79.92,39.18 79.92,40.64 79.92,40.68 79.93,42.27 80.08,43.08 80.26,43.47 80.39,43.75 80.79,44.78 81.04,44.89 82.16,44.45 82.63,44.66 82.83,45.15 82.6,45.66 81.49,46.09 81.39,46.32 82.24,48.5 82.24,48.51 82.61,49.46 86.62,59.76 87.49,60.63 87.7,60.63 88.21,61.15 88.21,61.35 88.68,61.82 88.91,61.82 89.4,62.31 89.4,62.54 89.84,62.98 90.1,64.47 90.1,65.2 90.31,65.41 v1(90.33,65.41)
PE_CPU1_SLOT2_RX_DP<7>: length 41.3
  TOP w0.127: v1(88.57,66.88) 88.32,66.64 88.32,64.47 88.47,64.31 J4.23
  IN2 w0.165: v1(88.57,66.88) 88.34,66.65 88.34,66.65 88.33,66.65 88.33,64.49 85.02,58.78 81.76,53.14 78.8,47.79 78.87,47.55 78.55,46.97 78.31,46.9 77.99,46.32 78.06,46.08 77.74,45.5 77.5,45.43 75.93,42.61 75.93,39.2 74.9,38.16 74.9,34.69 75.05,34.54 75.19,34.47 75.42,34.54 J2.A47
PE_CPU1_SLOT2_RX_DP<8>: length 36.1
  TOP w0.127: v1(66.78,65.41) 66.57,65.2 66.57,64.47 66.72,64.31 J5.2
  IN2 w0.165: v1(66.78,65.41) 66.56,65.19 66.56,64.71 66.71,63.81 66.72,63.8 66.78,63.44 67.68,61.26 68.41,60.96 69.52,58.27 69.59,57.36 68.89,53.32 68.95,52.8 69.9,40.75 69.91,40.53 69.91,40.52 69.91,39.42 70.91,38.43 70.91,34.52 70.68,34.3 70.49,34.2 70.42,33.98 J2.A52
PE_CPU1_SLOT2_RX_DP<9>: length 38.5
  TOP w0.127: v1(65.04,66.88) 64.77,66.62 64.77,64.47 64.92,64.31 J5.5
  IN2 w0.165: v1(65.04,66.88) 64.78,66.63 64.78,65.06 64.82,64.55 65.4,62.58 66.15,61.21 66.2,61.08 66.66,58.51 66.71,58.21 67.04,55.66 65.91,42.78 65.91,39.42 66.95,38.38 66.95,34.56 66.68,34.3 66.49,34.2 66.42,33.98 J2.A56
PE_CPU1_SLOT2_RX_DP<10>: length 36
  TOP w0.127: v1(63.18,65.41) 62.97,65.2 62.97,64.47 63.12,64.31 J5.8
  IN2 w0.165: v1(63.18,65.41) 62.95,65.18 62.95,64.7 63.11,63.76 63.34,63.22 63.54,62.56 64.36,60.88 64.51,60.5 65.45,55.2 61.84,41.61 61.84,40.64 61.91,40.56 61.91,39.38 62.9,38.39 62.9,34.52 62.68,34.3 62.49,34.2 62.49,34.2 62.42,33.98 J2.A60
PE_CPU1_SLOT2_RX_DP<11>: length 38.5
  TOP w0.127: J5.11 61.32,64.31 61.17,64.47 61.17,66.62 v1(61.43,66.88)
  IN2 w0.165: J2.A64 58.42,33.98 58.49,34.2 58.49,34.2 58.68,34.3 58.9,34.51 58.9,38.4 57.92,39.37 57.92,41.57 58.06,45.36 61.63,61.5 61,65.08 61.1,65.62 61.19,66.17 61.19,66.65 v1(61.43,66.88)
PE_CPU1_SLOT2_RX_DP<12>: length 37.6
  TOP w0.127: J5.14 59.52,64.31 59.37,64.47 59.37,65.2 v1(59.58,65.41)
  IN2 w0.165: J2.A68 54.42,33.98 54.49,34.2 54.68,34.3 54.92,34.53 54.92,38.36 53.94,39.34 53.94,40.56 53.63,40.87 53.63,42.83 54.16,43.58 54.07,44.1 53.79,44.3 53.74,44.57 53.9,44.79 54.17,44.84 54.45,44.64 54.96,44.73 55.32,45.25 59.24,56.89 59.48,58.15 59.32,59.31 59.81,62.08 59.35,64.73 59.35,65.18 v1(59.58,65.41)
PE_CPU1_SLOT2_RX_DP<13>: length 39.9
  TOP w0.127: J5.17 57.72,64.31 57.57,64.47 57.57,66.63 v1(57.82,66.88)
  IN2 w0.165: J2.A72 50.42,33.98 50.49,34.2 50.68,34.3 50.92,34.53 50.92,38.37 49.92,39.36 49.92,43.46 57.51,58.27 57.59,58.74 57.59,66.65 v1(57.82,66.88)
PE_CPU1_SLOT2_RX_DP<14>: length 38.8
  TOP w0.127: v1(55.98,65.41) 55.77,65.2 55.77,64.47 55.92,64.31 J5.20
  IN2 w0.165: v1(55.98,65.41) 55.75,65.18 55.75,59.61 55.55,58.45 55.55,58.43 55.51,58.4 55.04,57.64 53.38,57.26 50.83,53.18 51.22,51.51 45.93,43.05 45.94,40.59 45.94,39.35 46.92,38.37 46.92,34.56 46.64,34.27 46.49,34.2 46.42,33.98 J2.A76
PE_CPU1_SLOT2_RX_DP<15>: length 41.4
  TOP w0.127: v1(54.22,66.88) 53.97,66.64 53.97,64.47 54.12,64.31 J5.23
  IN2 w0.165: v1(54.22,66.88) 53.99,66.65 53.99,65.05 53.98,65.02 53.98,63.99 53.59,62.29 53.56,62.25 41.92,43.22 41.92,39.34 42.92,38.34 42.92,34.53 42.68,34.3 42.64,34.27 42.49,34.2 42.42,33.98 J2.A80
PE_CPU1_SLOT2_TX_DN<0>: length 25.1
  TOP w0.127: J4.48 100.47,59.64 100.63,59.48 100.63,58.78 101.86,53.55 107.52,44.58 107.52,43.28 v1(107.3,43.05)
  BOTTOM w0.127: v1(107.3,43.05) 107.58,42.77 107.58,39.13 107.94,38.76 108.1,38.69 108.15,38.52 J2.B15
PE_CPU1_SLOT2_TX_DN<1>: length 24.2
  TOP w0.127: J4.45 98.67,59.64 98.83,59.48 98.83,58.9 98.69,58.12 99.31,53.33 103.56,43.84 103.56,43.29 v1(103.33,43.05)
  BOTTOM w0.127: J2.B20 103.15,39.01 103.32,38.95 103.44,39.01 103.58,39.15 103.58,40.26 103.43,40.4 103.43,40.78 103.58,40.93 103.58,41.31 103.43,41.46 103.43,41.84 103.58,41.99 103.58,42.8 v1(103.33,43.05)
PE_CPU1_SLOT2_TX_DN<2>: length 23.5
  TOP w0.127: J4.42 96.87,59.64 97.03,59.48 97.03,59.17 97.31,54.62 99.56,43.73 99.56,43.29 v1(99.33,43.05)
  BOTTOM w0.127: v1(99.33,43.05) 99.58,42.8 99.58,41.98 99.43,41.83 99.43,41.45 99.58,41.3 99.58,40.92 99.43,40.77 99.43,40.39 99.58,40.24 99.58,39.15 99.44,39.01 99.32,38.95 99.15,39.01 J2.B24
PE_CPU1_SLOT2_TX_DN<3>: length 23.2
  TOP w0.127: J4.39 95.07,59.64 95.23,59.48 95.23,58.85 95.05,51.09 95.56,43.57 95.56,43.56 95.56,43.29 v1(95.33,43.05)
  BOTTOM w0.127: v1(95.33,43.05) 95.58,42.8 95.58,42.15 95.43,42 95.43,41.42 95.58,41.27 95.58,40.89 95.43,40.74 95.43,40.36 95.58,40.21 95.58,39.15 95.44,39.01 95.32,38.95 95.15,39.01 J2.B28
PE_CPU1_SLOT2_TX_DN<4>: length 23.7
  TOP w0.127: v1(89.33,43.05) 89.56,43.29 89.56,43.61 93.43,58.1 93.43,59.48 93.27,59.64 J4.36
  BOTTOM w0.127: J2.B34 89.15,39.01 89.32,38.95 89.44,39.01 89.58,39.15 89.58,40.29 89.43,40.44 89.43,40.82 89.58,40.97 89.58,41.35 89.43,41.5 89.43,41.88 89.58,42.03 89.58,42.8 v1(89.33,43.05)
PE_CPU1_SLOT2_TX_DN<5>: length 24.4
  TOP w0.127: J4.33 91.47,59.64 91.63,59.48 91.63,58.08 85.56,43.61 85.56,43.29 v1(85.33,43.05)
  BOTTOM w0.127: v1(85.33,43.05) 85.58,42.8 85.58,42.02 85.43,41.87 85.43,41.49 85.58,41.34 85.58,40.96 85.43,40.81 85.43,40.43 85.58,40.28 85.58,39.15 85.44,39.01 85.32,38.95 85.15,39.01 J2.B38
PE_CPU1_SLOT2_TX_DN<6>: length 25.3
  TOP w0.127: J4.30 89.67,59.64 89.83,59.48 89.83,58.85 81.56,43.65 81.56,43.29 v1(81.33,43.05)
  BOTTOM w0.127: J2.B42 81.15,39.01 81.32,38.95 81.44,39.01 81.58,39.15 81.58,40.26 81.43,40.4 81.43,40.78 81.58,40.93 81.58,41.31 81.43,41.46 81.43,41.84 81.58,41.99 81.58,42.8 v1(81.33,43.05)
PE_CPU1_SLOT2_TX_DN<7>: length 26.6
  TOP w0.127: J4.27 87.87,59.64 88.03,59.48 88.03,58.58 87.87,58.18 87.79,58.03 77.56,43.82 77.56,43.54 77.56,43.29 v1(77.33,43.05)
  BOTTOM w0.127: J2.B46 77.15,39.01 77.32,38.95 77.44,39.01 77.58,39.15 77.58,40.28 77.43,40.43 77.43,40.81 77.58,40.96 77.58,41.34 77.43,41.49 77.43,41.87 77.58,42.02 77.58,42.8 v1(77.33,43.05)
PE_CPU1_SLOT2_TX_DN<8>: length 24.3
  TOP w0.127: v1(71.3,43.05) 71.5,43.26 71.5,43.83 66.29,58.09 66.28,58.14 66.28,59.48 66.12,59.64 J5.48
  BOTTOM w0.127: v1(71.3,43.05) 71.58,42.77 71.58,39.13 71.94,38.76 72.1,38.69 72.15,38.52 J2.B51
PE_CPU1_SLOT2_TX_DN<9>: length 23.7
  TOP w0.127: v1(67.3,43.05) 67.51,43.27 67.51,43.86 64.63,58.26 64.48,59.12 64.48,59.48 64.32,59.64 J5.45
  BOTTOM w0.127: v1(67.3,43.05) 67.58,42.77 67.58,39.13 67.94,38.76 68.1,38.69 68.15,38.52 J2.B55
PE_CPU1_SLOT2_TX_DN<10>: length 23.3
  TOP w0.127: v1(63.42,43.05) 63.64,43.27 63.64,43.82 63.64,43.83 62.68,58 62.68,59.48 62.52,59.64 J5.42
  BOTTOM w0.127: J2.B59 64.15,38.52 64.1,38.69 64.1,38.69 63.94,38.76 63.61,39.09 63.61,42.86 v1(63.42,43.05)
PE_CPU1_SLOT2_TX_DN<11>: length 23.4
  TOP w0.127: J5.39 60.72,60.07 60.72,59.64 60.88,59.48 60.88,57.64 59.73,44.55 59.65,44.1 59.65,43.28 v1(59.42,43.05)
  BOTTOM w0.127: J2.B63 60.15,38.52 60.1,38.69 60.1,38.69 59.94,38.76 59.61,39.09 59.61,42.86 v1(59.42,43.05)
PE_CPU1_SLOT2_TX_DN<12>: length 23.7
  TOP w0.127: v1(55.42,43.05) 55.66,43.29 55.66,43.29 55.68,43.31 55.68,44.07 57.86,52.05 57.86,52.06 57.94,52.32 59.08,57.84 59.08,58.55 59.08,59.48 58.92,59.64 J5.36
  BOTTOM w0.127: v1(55.42,43.05) 55.61,42.86 55.61,39.09 55.94,38.76 56.1,38.69 56.1,38.69 56.15,38.52 J2.B67
PE_CPU1_SLOT2_TX_DN<13>: length 24.6
  TOP w0.127: v1(51.3,43.05) 51.52,43.28 51.52,44.62 57.28,57.83 57.28,59.48 57.12,59.64 J5.33
  BOTTOM w0.127: J2.B71 52.15,38.52 52.1,38.69 51.94,38.76 51.58,39.13 51.58,42.77 v1(51.3,43.05)
PE_CPU1_SLOT2_TX_DN<14>: length 25.5
  TOP w0.127: v1(47.3,43.05) 47.5,43.26 47.5,43.76 47.5,43.92 55.48,57.91 55.48,59.48 55.32,59.64 J5.30
  BOTTOM w0.127: J2.B75 48.15,38.52 48.1,38.69 47.94,38.76 47.58,39.13 47.58,42.77 v1(47.3,43.05)
PE_CPU1_SLOT2_TX_DN<15>: length 26.5
  TOP w0.127: J5.27 53.52,59.64 53.68,59.48 53.68,58.7 43.53,44.09 43.53,43.29 v1(43.3,43.05)
  BOTTOM w0.127: J2.B79 44.15,38.52 44.1,38.69 44.1,38.69 43.98,38.74 43.58,39.15 43.58,42.77 v1(43.3,43.05)
PE_CPU1_SLOT2_TX_DP<0>: length 25
  TOP w0.127: v1(108.06,43.05) 107.81,43.3 107.81,44.66 102.14,53.67 100.92,58.81 100.92,59.48 101.07,59.64 J4.49
  BOTTOM w0.127: J2.B14 108.4,39.01 108.23,38.95 108.11,39.01 107.87,39.25 107.87,40.22 108.02,40.37 108.02,40.75 107.87,40.9 107.87,41.28 108.02,41.43 108.02,41.81 107.87,41.96 107.87,42.87 v1(108.06,43.05)
PE_CPU1_SLOT2_TX_DP<1>: length 24.3
  TOP w0.127: J4.46 99.27,59.64 99.12,59.48 99.12,58.88 98.98,58.12 99.6,53.41 103.85,43.9 103.85,43.29 v1(104.09,43.05)
  BOTTOM w0.127: J2.B19 103.4,38.52 103.45,38.69 103.61,38.76 103.87,39.03 103.87,42.84 v1(104.09,43.05)
PE_CPU1_SLOT2_TX_DP<2>: length 23.5
  TOP w0.127: v1(100.09,43.05) 99.85,43.29 99.85,43.76 97.6,54.66 97.32,59.18 97.32,59.48 97.47,59.64 J4.43
  BOTTOM w0.127: v1(100.09,43.05) 99.87,42.84 99.87,39.03 99.61,38.76 99.45,38.69 99.4,38.52 J2.B23
PE_CPU1_SLOT2_TX_DP<3>: length 23.3
  TOP w0.127: J4.40 95.67,59.64 95.52,59.48 95.52,58.84 95.34,51.1 95.85,43.58 95.85,43.56 95.85,43.29 v1(96.09,43.05)
  BOTTOM w0.127: v1(96.09,43.05) 95.87,42.84 95.87,39.03 95.61,38.76 95.45,38.69 95.4,38.52 J2.B27
PE_CPU1_SLOT2_TX_DP<4>: length 23.8
  TOP w0.127: J4.37 93.87,59.64 93.72,59.48 93.72,58.06 89.85,43.57 89.85,43.29 v1(90.09,43.05)
  BOTTOM w0.127: v1(90.09,43.05) 89.87,42.84 89.87,39.03 89.61,38.76 89.45,38.69 89.4,38.52 J2.B33
PE_CPU1_SLOT2_TX_DP<5>: length 24.5
  TOP w0.127: v1(86.09,43.05) 85.85,43.29 85.85,43.55 91.92,58.02 91.92,59.48 92.07,59.64 J4.34
  BOTTOM w0.127: J2.B37 85.4,38.52 85.45,38.69 85.61,38.76 85.87,39.03 85.87,42.84 v1(86.09,43.05)
PE_CPU1_SLOT2_TX_DP<6>: length 25.4
  TOP w0.127: J4.31 90.27,59.64 90.12,59.48 90.12,58.78 81.85,43.58 81.85,43.29 v1(82.09,43.05)
  BOTTOM w0.127: J2.B41 81.4,38.52 81.45,38.69 81.61,38.76 81.87,39.03 81.87,42.84 v1(82.09,43.05)
PE_CPU1_SLOT2_TX_DP<7>: length 26.6
  TOP w0.127: v1(78.09,43.05) 77.85,43.29 77.85,43.54 77.85,43.72 88.04,57.88 88.13,58.06 88.32,58.53 88.32,59.48 88.47,59.64 J4.28
  BOTTOM w0.127: J2.B45 77.4,38.52 77.45,38.69 77.61,38.76 77.87,39.03 77.87,42.84 v1(78.09,43.05)
PE_CPU1_SLOT2_TX_DP<8>: length 24.2
  TOP w0.127: J5.49 66.72,60.15 66.72,59.64 66.57,59.48 66.57,58.2 66.57,58.19 71.79,43.88 71.79,43.32 v1(72.06,43.05)
  BOTTOM w0.127: J2.B50 72.4,39.01 72.23,38.95 72.11,39.01 71.87,39.25 71.87,40.33 72.02,40.48 72.02,40.86 71.87,41.01 71.87,41.39 72.02,41.54 72.02,41.92 71.87,42.07 71.87,42.87 v1(72.06,43.05)
PE_CPU1_SLOT2_TX_DP<9>: length 23.5
  TOP w0.127: J5.46 64.92,59.64 64.77,59.48 64.77,59.15 64.91,58.32 67.81,43.89 67.81,43.3 v1(68.06,43.05)
  BOTTOM w0.127: J2.B54 68.4,39.01 68.23,38.95 68.11,39.01 67.87,39.25 67.87,40.21 68.02,40.36 68.02,40.74 67.87,40.89 67.87,41.27 68.02,41.42 68.02,41.8 67.87,41.95 67.87,42.87 v1(68.06,43.05)
PE_CPU1_SLOT2_TX_DP<10>: length 23.3
  TOP w0.127: J5.43 63.12,59.64 62.97,59.48 62.97,58.02 63.93,43.9 63.93,43.89 63.93,43.3 v1(64.18,43.05)
  BOTTOM w0.127: v1(64.18,43.05) 63.91,42.78 63.91,41.96 64.05,41.81 64.05,41.43 63.91,41.28 63.91,40.9 64.05,40.75 64.05,40.37 63.91,40.22 63.91,39.21 64.11,39.01 64.23,38.95 64.4,39.01 J2.B58
PE_CPU1_SLOT2_TX_DP<11>: length 23.3
  TOP w0.127: J5.40 61.32,59.64 61.17,59.48 61.17,57.63 60.02,44.51 59.94,44.08 59.94,43.3 v1(60.18,43.05)
  BOTTOM w0.127: J2.B62 60.4,39.01 60.23,38.95 60.11,39.01 59.91,39.21 59.91,40.21 60.05,40.36 60.05,40.74 59.91,40.89 59.91,41.27 60.05,41.42 60.05,41.8 59.91,41.95 59.91,42.78 v1(60.18,43.05)
PE_CPU1_SLOT2_TX_DP<12>: length 23.7
  TOP w0.127: v1(56.18,43.05) 55.97,43.27 55.97,44.03 58.22,52.26 59.37,57.78 59.37,59.48 59.52,59.64 J5.37
  BOTTOM w0.127: J2.B66 56.4,39.01 56.23,38.95 56.11,39.01 55.91,39.21 55.91,40.1 56.06,40.25 56.06,40.63 55.91,40.78 55.91,41.16 56.06,41.31 56.06,41.69 55.91,41.83 55.91,42.78 v1(56.18,43.05)
PE_CPU1_SLOT2_TX_DP<13>: length 24.4
  TOP w0.127: v1(52.06,43.05) 51.82,43.29 51.82,44.56 57.57,57.77 57.57,59.48 57.72,59.64 57.72,60.07 J5.34
  BOTTOM w0.127: v1(52.06,43.05) 51.87,42.87 51.87,42.09 52.02,41.95 52.02,41.56 51.87,41.42 51.87,41.03 52.02,40.89 52.02,40.51 51.87,40.36 51.87,39.25 52.11,39.01 52.23,38.95 52.4,39.01 J2.B70
PE_CPU1_SLOT2_TX_DP<14>: length 25.4
  TOP w0.127: v1(48.06,43.05) 47.79,43.32 47.79,43.77 47.79,43.84 55.77,57.83 55.77,59.48 55.92,59.64 J5.31
  BOTTOM w0.127: J2.B74 48.4,39.01 48.23,38.95 48.11,39.01 47.87,39.25 47.87,40.31 48.02,40.46 48.02,40.84 47.87,40.99 47.87,41.37 48.02,41.52 48.02,41.9 47.87,42.05 47.87,42.87 v1(48.06,43.05)
PE_CPU1_SLOT2_TX_DP<15>: length 26.4
  TOP w0.127: v1(44.06,43.05) 43.82,43.29 43.82,44 53.97,58.61 53.97,59.48 54.12,59.64 J5.28
  BOTTOM w0.127: v1(44.06,43.05) 43.87,42.87 43.87,42.01 43.95,41.93 44.03,41.85 44.03,41.47 43.95,41.39 43.87,41.31 43.87,40.93 43.95,40.84 44.03,40.76 44.03,40.38 43.95,40.3 43.87,40.22 43.87,39.27 44.16,38.98 44.23,38.95 44.4,39.01 J2.B78
PU_EMC1413_ADDR: length 4
  TOP w0.117: U2.7 75.8,28.2 75.99,28.02 75.99,26.82 v1(76.54,26.26) 76.95,26.67 R87.2
PU_EMC1413_ALERT_N: length 3.2
  TOP w0.117: R86.2 77.16,27.53 v1(76.57,27.53) 76.57,28.02 75.88,28.7 U2.8
RISER_WAKE_N: length 24.1
  TOP w0.117: v1(111.39,21.56) 111.24,21.72 R49.2 R61.2 R48.2
  BOTTOM w0.117: v2(110.91,22.53) 111.39,22.05 v1(111.39,21.56) 111.82,21.13 111.82,18.62 110.68,17.48 110.68,17.14 110.4,16.87 110.4,15.47 110.73,15.14 110.73,14.55 113.78,11.51 J3.B11
RST_PCA9548_N: length 3.2
  TOP w0.117: R62.2 134.13,38.58 v1(134.81,37.9) U1.3
RST_PE_N: length 32.2
  TOP w0.117: U4.2 116.45,24.83 v1(116.96,24.33) 114.47,24.33 114.16,24.64 114.16,25.22 114.07,25.32 U6.2 113.88,25.16 113.88,24.89 113.76,24.77 113.76,21.14 113.3,20.68 113.3,19.08 114.56,17.82 114.56,14.54 114.14,14.12 113.17,14.12 110.61,11.56 110.61,10.03 110.99,9.65 113.02,9.65 113.78,8.89 J3.A11
RST_PE_SLOT1_N: length 15.1
  TOP w0.117: v1(113.42,26.64) 114.03,26.64 114.68,27.29 U6.4
  BOTTOM w0.117: J1.A11 113.78,15.49 114.8,16.51 114.8,17.63 112.64,19.79 112.64,25.52 113.42,26.31 v1(113.42,26.64)
RST_PE_SLOT2_N: length 15.2
  TOP w0.117: U4.4 117.1,27.02 116.84,26.75 114.75,26.75 114.14,26.14 113.12,26.14 112.84,26.42 112.84,29.64 112,30.48 112,33.49 J2.A11
SLOT1_B12_PWRBRK_N: length 11
  TOP w0.117: R75.2 v1(112.25,28.42)
  BOTTOM w0.117: J1.B12 110.05,20.17 110.05,22.89 110.78,23.61 110.78,24.93 112.48,26.64 112.48,28.19 v1(112.25,28.42)
SLOT1_B30_PWRBRK_N: length 22.2
  TOP w0.117: v1(109.72,23.88) 110.48,23.88 111.82,25.22 R76.2
  BOTTOM w0.117: v1(109.72,23.88) 106.59,20.75 93.51,20.75 92.78,20.02 J1.B30
SLOT1_GF_PRSNT_N: length 22.2
  TOP w0.117: J1.A1 129.95,14.94 130.29,14.61 130.29,10.59 129.58,9.88 125.69,9.88 v1(124.83,9.02) 124.58,8.76 124.58,8.19 124.54,8.16 124.54,8.16 124.42,8.04 123.78,7.39 J3.A1
SLOT1_PWRBRK_N: length 3.9
  TOP w0.117: U7.4 111.35,27 v1(111.52,27) R75.1 R76.1
  BOTTOM w0.117: R90.2 111.34,27.18 v1(111.52,27)
SLOT1_WAKE_N: length 1.9
  TOP w0.117: R11.1 112.26,23.37 v1(111.88,23.75) 111.24,23.11 R49.1
SLOT1_WAKE_R_N: length 5.4
  TOP w0.117: J1.B11 112.26,18.96 R11.2
SLOT2_B12_PWRBRK_N: length 9.2
  TOP w0.117: J2.B12 110.78,40.63 112.69,42.55 112.69,45.09 113.4,45.8 113.4,46.91 112.95,47.36 R73.2
SLOT2_B30_PWRBRK_N: length 25.2
  TOP w0.117: R74.2 v1(111.6,48.08)
  BOTTOM w0.117: J2.B30 92.78,43.54 97.3,48.06 111.57,48.06 v1(111.6,48.08)
SLOT2_JTAG_TCK: length 3.5
  TOP w0.117: R81.2 119.78,32.3 J2.A5
SLOT2_JTAG_TDI: length 1.5
  TOP w0.117: J2.A6 118.78,32.81 118.35,32.38 R78.2
SLOT2_JTAG_TDO: length 3.5
  TOP w0.117: J2.A7 117.78,32.82 117.34,32.38 R79.2
SLOT2_JTAG_TMS: length 1.6
  TOP w0.117: J2.A8 116.32,32.81 R80.2
SLOT2_JTAG_TRST_N: length 7.2
  TOP w0.117: v1(112.09,41.21) R77.2
  BOTTOM w0.117: v1(112.09,41.21) 112.09,40.76 115.08,37.76 J2.B9
SLOT2_PRSNT_N: length 4.4
  TOP w0.117: J2.A1 125.25,33.78 R4.1
SLOT2_PWRBRK_N: length 4.1
  TOP w0.117: U5.4 111.99,45.3 111.62,45.67 v1(111.62,45.85) 111.6,45.87 R74.1 R73.1
  BOTTOM w0.117: v1(111.62,45.85) 111.37,45.59 R89.2
SLOT2_WAKE_N: length 9.3
  TOP w0.117: R3.1 110.72,31.1 108.49,28.86 108.49,28.4 108.93,27.97 v1(108.93,24.13) 108.93,23.77 109.21,23.5 R48.1
SLOT2_WAKE_R_N: length 10
  TOP w0.117: R3.2 109.97,32.66 109.97,33.78 110.61,34.42 110.61,35.66 110.35,35.92 110.35,37.13 111.4,38.18 113.35,38.18 J2.B11
TEMP_SEN1_DN: length 165.6
  TOP w0.254: U2.3 69.89,28.7 69.81,28.78 38.03,28.78 35.42,31.39 35.42,44.51 37.35,46.43 39.8,46.43 v1(39.99,46.62) ; v1(140.27,55.61) 140.72,55.17 142.01,55.17 C24.2 142.37,55.24 143.5,55.24 143.65,55.4 145.99,55.4 Q6.2
  BOTTOM w0.254: v1(140.27,55.61) 139.83,55.17 78.42,55.17 69.69,46.43 40.18,46.43 v1(39.99,46.62)
TEMP_SEN1_DP: length 165.2
  TOP w0.254: v1(39.99,45.86) 39.8,46.05 37.5,46.05 35.8,44.35 35.8,31.55 38.19,29.16 69.79,29.16 69.83,29.2 U2.2 ; v1(140.27,54.34) 140.72,54.79 142.03,54.79 C24.1 142.5,54.86 144.15,54.86 Q6.3 144.56,55.02 145.5,55.02 146.28,54.24 Q6.1
  BOTTOM w0.254: v1(39.99,45.86) 40.18,46.05 69.84,46.05 78.58,54.79 139.83,54.79 v1(140.27,54.34)
TEMP_SEN2_DN: length 60.6
  TOP w0.254: Q5.2 12.49,29.57 14.82,29.57 14.97,29.72 16.1,29.72 C23.2 16.39,29.72 17.77,29.72 v1(18.66,28.83) 19.55,29.72 20.66,29.72 22.94,27.43 69.18,27.43 69.51,27.76 69.84,27.76 69.9,27.7 U2.5
TEMP_SEN2_DP: length 61.5
  TOP w0.254: U2.4 69.9,28.2 69.84,28.14 69.35,28.14 69.02,27.81 23.1,27.81 20.82,30.1 19.55,30.1 v1(18.66,30.99) 17.77,30.1 16.52,30.1 C23.1 15.97,30.1 14.32,30.1 Q5.3 13.92,29.95 12.97,29.95 12.2,30.72 Q5.1
UNNAMED_11_9DBL411B_I133_OE0: length 16.4
  TOP w0.117: U8.1 v1(95.77,29.89) ; U8.16 103.97,27.29 104.33,26.92 v1(104.71,26.92) R18.2
  BOTTOM w0.117: v1(104.71,26.92) 102.83,26.92 102.15,27.61 102.15,30.28 101.66,30.76 97.52,30.76 96.65,29.89 v1(95.77,29.89)
UNNAMED_11_9DBL411B_I133_OE2: length 15.3
  TOP w0.117: R19.2 105.13,23.88 v1(104.49,24.52) 103.67,25.34 U8.13 ; U8.6 96.17,26.64 95.94,26.4 v1(95.94,25.57)
  BOTTOM w0.117: v1(104.49,24.52) 103.09,23.11 98.39,23.11 v1(95.94,25.57)
UNNAMED_12_2N7002_I1_G: length 2.4
  TOP w0.117: Q1.G 117.6,48.43 v1(118.33,47.7) 117.61,46.98 R32.2
UNNAMED_12_2N7002_I5_G: length 2.2
  TOP w0.117: Q3.G 120.9,48.43 v1(121.76,47.57) 121.76,47.45 R34.2
UNNAMED_12_2N7002_I21_G: length 2.9
  TOP w0.117: Q2.G 118.86,27.03 v1(118.86,25.91) 120,25.91 120.24,25.67 R33.2
UNNAMED_12_2N7002_I22_G: length 2.4
  TOP w0.117: R35.2 123.03,26.41 v1(123.03,26.54) 122.35,27.22 Q4.G
UNNAMED_13_AT24C64D_I41_A0: length 4
  TOP w0.117: R43.1 R60.2 143.93,42.31 v1(143.9,42.34) 143.52,42.73 U3.1
UNNAMED_13_AT24C64D_I41_A1: length 4
  TOP w0.117: R45.1 R44.2 143.98,44.35 v1(143.96,44.32) 143.63,44 U3.2
UNNAMED_13_AT24C64D_I41_A2: length 4.3
  TOP w0.117: R46.2 R47.1 144.21,46.38 v1(144.11,46.28) 143.1,45.27 U3.3
UNNAMED_13_AT24C64D_I41_WP: length 2.4
  TOP w0.117: R42.1 135.08,43.48 v1(135.32,43.48) 136.12,43.48 U3.7

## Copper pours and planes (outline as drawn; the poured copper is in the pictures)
GND on TOP (solid shape): 39.99,64.9 39.99,51.44 39.87,51.31 36.69,51.31 36.18,51.82 36.18,65.15 36.44,65.41 39.49,65.41
GND on TOP (solid shape): 101.77,30.2 101.77,23.83 101.56,23.62 98.36,23.62 98.18,23.8 98.18,30.15 98.41,30.38 101.59,30.38
GND on TOP (solid shape): 95.75,23.62 95.75,21.82 95.49,21.56 93.26,21.56 93.1,21.72 93.1,23.39 93.28,23.57 94.93,23.57 95.06,23.7 95.67,23.7
GND on TOP (solid shape): 29.71,68.33 29.71,63.5 29.58,63.37 27.17,63.37 26.91,63.12 26.91,51.82 26.66,51.56 22.98,51.56 22.72,51.82 22.72,67.69 23.86,68.83 29.2,68.83
GND on TOP (solid shape): 148,75.89 149.05,75.45 149.49,74.4 149.49,10.41 149.05,9.35 148,8.92 126.53,8.92 126.45,8.99 126.45,9.32 126.56,9.42 148,9.42 148.69,9.71 148.98,10.41 148.98,74.4 148.69,75.1 148,75.38 105.04,75.38 104.97,75.46 104.97,75.84 105.02,75.89
GND on TOP (solid shape): 49.62,75.84 49.62,75.41 49.59,75.38 2,75.38 1.3,75.1 1.02,74.4 1.02,12 1.3,11.3 2,11.02 6.52,11.02 6.74,10.79 7.31,10.79 7.53,11.02 41.06,11.02 41.11,10.99 41.13,10.94 41.13,9.52 40.96,9.35 40.67,9.35 40.62,9.4 40.62,10.51 2,10.51 0.94,10.94 0.51,12 0.51,74.4 0.94,75.45 2,75.89 49.57,75.89
GND on TOP (solid shape): outline of 343 points within 0.95,62 15.95,72
GND on TOP (solid shape): outline of 343 points within 133.55,61 148.55,71
GND on TOP (solid shape): outline of 343 points within 133.55,11 148.55,21
GND on BOTTOM (solid shape): 101.77,30.2 101.77,23.83 101.56,23.62 98.36,23.62 98.18,23.8 98.18,30.15 98.41,30.38 101.59,30.38
GND on BOTTOM (solid shape): 148,75.89 149.05,75.45 149.49,74.4 149.49,10.41 149.05,9.35 148,8.92 126.53,8.92 126.45,8.99 126.45,9.32 126.56,9.42 148,9.42 148.69,9.71 148.98,10.41 148.98,74.4 148.69,75.1 148,75.38 2,75.38 1.3,75.1 1.02,74.4 1.02,12 1.3,11.3 2,11.02 5.93,11.02 6.1,10.85 7.26,10.85 7.43,11.02 41.06,11.02 41.11,10.99 41.13,10.94 41.13,9.55 41.12,9.52 41.1,9.49 41.05,9.45 40.88,9.28 40.72,9.25 40.62,9.39 40.62,10.51 2,10.51 0.94,10.94 0.51,12 0.51,74.4 0.94,75.45 2,75.89
GND on BOTTOM (solid shape): outline of 343 points within 0.95,62 15.95,72
GND on BOTTOM (solid shape): outline of 343 points within 133.55,61 148.55,71
GND on BOTTOM (solid shape): outline of 343 points within 133.55,11 148.55,21
GND on GND (solid shape): outline of 8979 points within 0.51,5.66 149.49,75.89
GND on IN1 (solid shape): 148,75.89 149.05,75.45 149.49,74.4 149.49,10.41 149.05,9.35 148,8.92 126.53,8.92 126.45,8.99 126.45,9.32 126.56,9.42 148,9.42 148.69,9.71 148.98,10.41 148.98,74.4 148.69,75.1 148,75.38 2,75.38 1.3,75.1 1.02,74.4 1.02,12 1.3,11.3 2,11.02 6.34,11.02 6.46,10.9 7.34,10.9 7.46,11.02 41.06,11.02 41.11,10.99 41.13,10.94 41.13,9.52 40.96,9.35 40.7,9.35 40.62,9.42 40.62,10.51 2,10.51 0.94,10.94 0.51,12 0.51,74.4 0.94,75.45 2,75.89
